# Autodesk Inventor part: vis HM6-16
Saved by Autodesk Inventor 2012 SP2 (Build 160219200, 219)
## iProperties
Created: 2013-04
Part Number: vis HM6-16
Material: Default
Document SubType Name: Modeling
Designer: papa
Density: 1 g/cm^3
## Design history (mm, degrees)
node "vis HM6-161"
node "vis HM6-16"
node "Base1"
